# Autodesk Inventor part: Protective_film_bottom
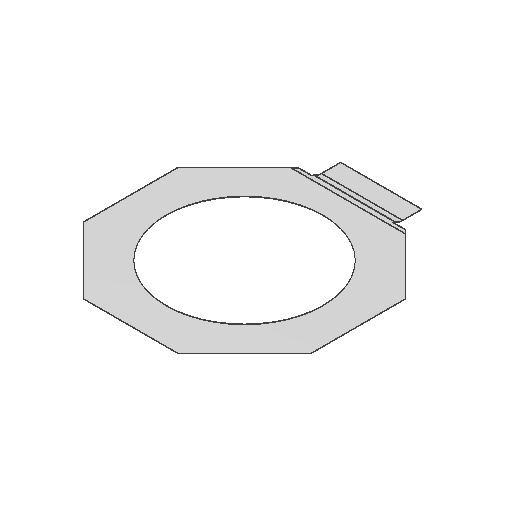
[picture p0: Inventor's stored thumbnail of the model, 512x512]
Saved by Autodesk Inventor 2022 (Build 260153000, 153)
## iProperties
Created: 2020-10
Part Number: Protective_film_bottom
Material: Generico
Document SubType Name: Modeling
Designer: admin
Density: 1 g/cm^3
Appearance: Default
Author: admin
Sending System: SolidWorks 2020
Last Author: Simon
Last Saved: 2020-10-30
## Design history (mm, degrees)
combine "Combine1"
node "Solido1"
